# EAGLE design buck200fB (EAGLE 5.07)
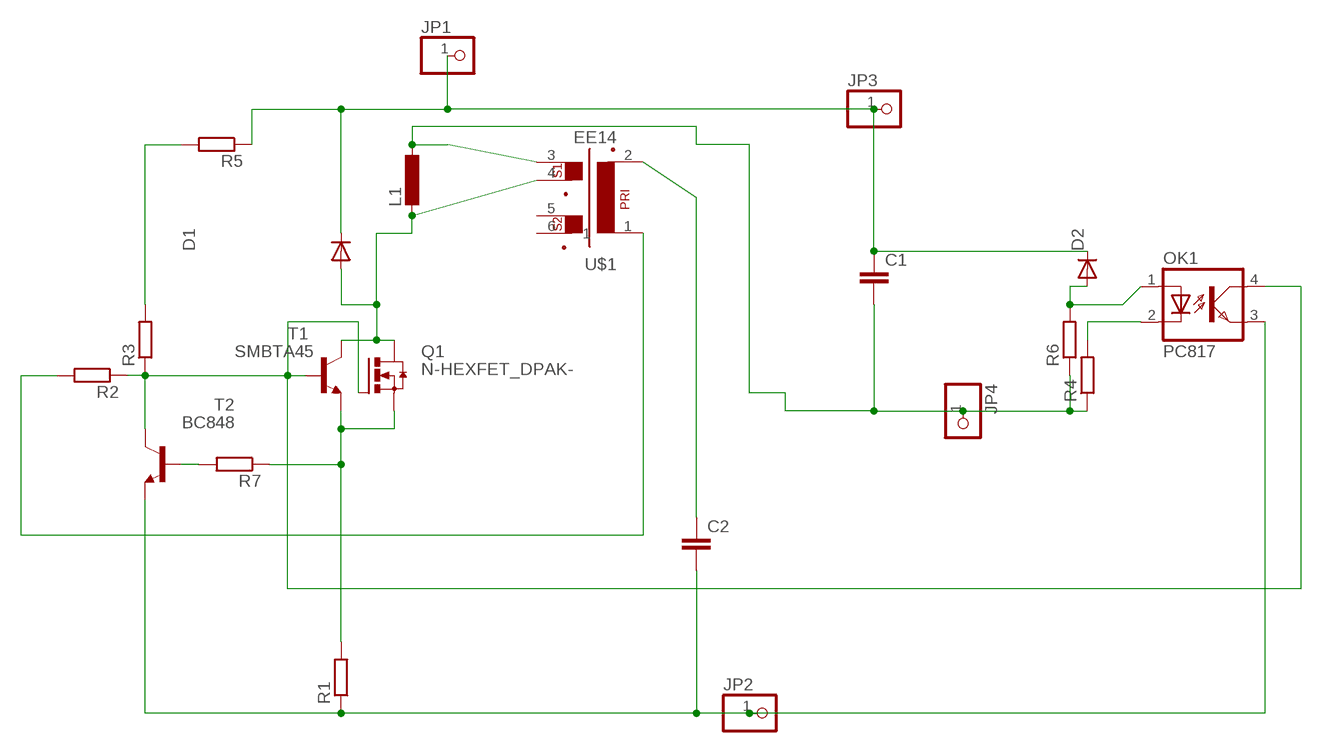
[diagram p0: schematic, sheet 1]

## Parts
C1  C-EU025-025X050  [C025-025X050]
C2  C-EUC0805  [C0805]
D1  DIODE-SMC  [SMC]
D2  DIODE-MINIMELF  [MINIMELF]
JP1  PINHD-1X11MM6  [1X1MM8]
JP2  PINHD-1X11MM6  [1X1MM8]
JP3  PINHD-1X11MM6  [1X1MM8]
JP4  PINHD-1X11MM6  [1X1MM8]
L1  L-EU0204/5  [0204/5]
OK1  PC817  [DIL04]
Q1  N-HEXFET_DPAK-  [TO252]
R1  R-EU_R0805  [R0805]
R2  R-EU_R0805  [R0805]
R3  R-EU_R1206  [R1206]
R4  R-EU_R0805  [R0805]
R5  R-EU_R1206  [R1206]
R6  R-EU_R0805  [R0805]
R7  R-EU_R0805  [R0805]
T1  SMBTA45  BC848  [SOT23]
T2  BC848  [SOT23]
U$1  EE14  [EE14]

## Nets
B1C2: OK1.4(COL) Q1.1(G) R2.1 R3.1 T1.B T2.C
C1: D1.A L1.2 Q1.3(D) T1.C U$1.4
EB: Q1.2(S) R1.2 R7.1 T1.E
N$1: R3.2 R5.2
N$3: R7.2 T2.B
N$4: R2.2 U$1.1
N$5: C1.2 JP4.1 L1.1 R4.1 R6.1 U$1.3
N$6: C2.1 U$1.2
N$7: D2.A OK1.1(A) R6.2
N$8: OK1.2(C) R4.2
V+: C1.1 D1.C D2.C JP1.1 JP3.1 R5.1
V-: C2.2 JP2.1 OK1.3(EMIT) R1.1 T2.E
Unconnected: U$1.5 U$1.6

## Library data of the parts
C1 C2 = rcl:C-EU: CAPACITOR, European symbol
D1 D2 = diode:DIODE-: DIODE
JP1-JP4 = pinhead:PINHD-1X1: PIN HEADER
L1 = rcl:L-EU: INDUCTOR, European symbol
OK1 = optocoupler:PC817: SHARP OPTO COUPLER
Q1 = transistor-power:N-HEXFET_?-*: HEXFET® Power MOSFET
R1-R7 = rcl:R-EU_: RESISTOR, European symbol
T1 T2 = transistor:BC848: NPN TRANSISTOR
U$1 = trafo:EE14

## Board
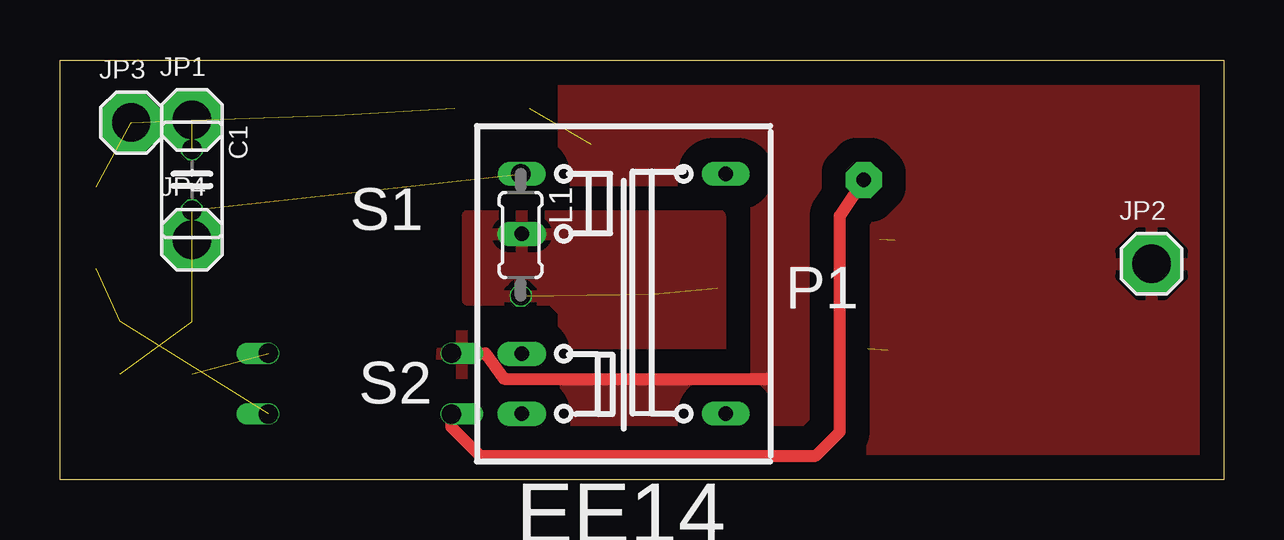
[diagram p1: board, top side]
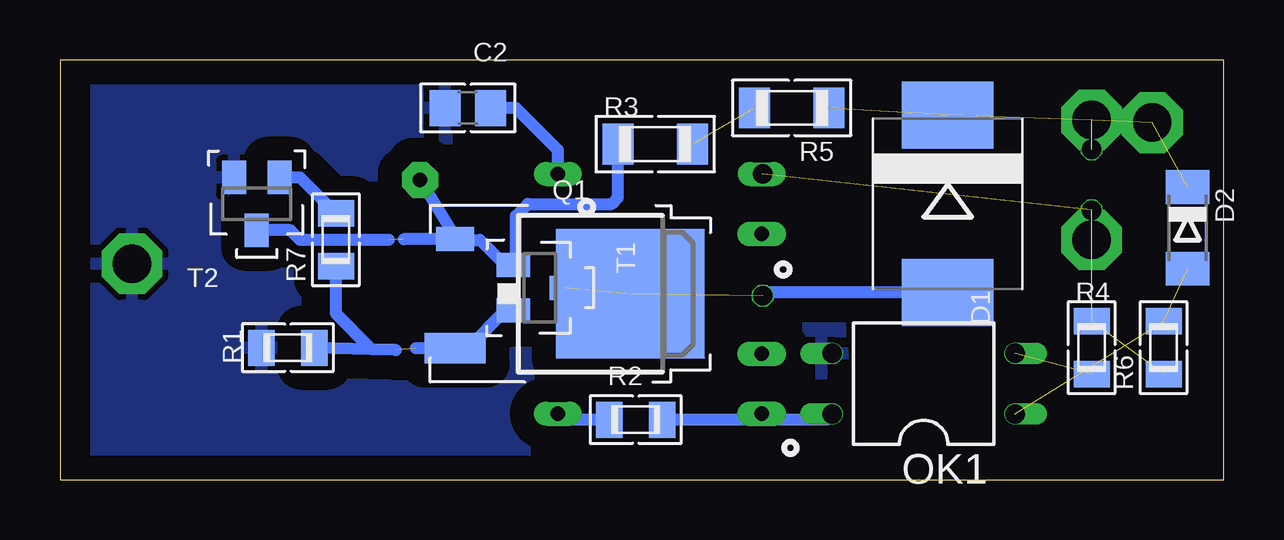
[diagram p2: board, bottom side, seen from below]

Size 48.5 x 17.5 mm. Coordinates in mm from the lower left corner, seen from the top.
Outline: 0,17.5 48.5,17.5 48.5,0 0,0 0,17.5
Copper layers (1*16): Top 0.035mm / dielectric 1.5mm / Bottom 0.035mm
Design rules "default": minimum track width 10mil, minimum drill 20mil, track to track 8mil, track to pad 8mil, pad to pad 8mil, via to via 8mil, smd to smd 8mil, copper to edge 40mil, drill to drill 8mil, minimum pad ring 1mil, minimum via ring 8mil, stop-mask expansion 4mil, vias tented up to drill 0mil, thermal gap 10mil

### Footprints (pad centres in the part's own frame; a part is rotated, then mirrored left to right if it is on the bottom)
C025-025X050 = drill 0.813 octagon: 1 -1.27,0; 2 1.27,0
C0805 = smd 1.3 x 1.5: 1 -0.95,0; 2 0.95,0
SMC = smd 2.8 x 3.8: A 3.7,0; C -3.7,0
MINIMELF = smd 1.4 x 1.8: A 1.7,0; C -1.7,0
1X1MM8 = drill 1.6 pad 2.54 octagon: 1 0,0
0204/5 = drill 0.813 octagon: 1 -2.54,0; 2 2.54,0
DIL04 = drill 0.813 offset: 1 -1.27,-3.81; 2 1.27,-3.81; 3 1.27,3.81; 4 -1.27,3.81
TO252 = smd 1 x 1.6: 1 -2.28,-3.53 | smd 1.27 x 2.54: 2 2.28,-3.53 | smd 5.4 x 6.2: 3 0,3.77
R0805 = smd 1.1 x 1.5: 1 -1.1,0; 2 1.1,0
R1206 = smd 1.3 x 1.7: 1 -1.55,0; 2 1.55,0
SOT23 = smd 1 x 1.4: B -0.95,-1.1; C 0,1.1; E 0.95,-1.1
EE14 = drill 0.6 pad 1 long: 1 4.25,-5; 2 4.25,5; 3 -4.25,5 | drill 0.6 pad 1.016 long: 4 -4.25,2.5; 5 -4.25,-2.5; 6 -4.25,-5

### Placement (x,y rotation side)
C1  5.5,12.5 270 top
C2  31.5,15.5 180 bottom
D1  11.5,11.5 270 bottom
D2  1.5,10.5 270 bottom
JP1  5.5,15 0 top
JP2  45.5,9 0 top
JP3  2.97,14.89 0 top
JP4  5.5,10 0 top
L1  19.2,10.2 270 top
OK1  12.5,4 90 bottom
Q1  28.5,7.75 270 bottom
R1  39,5.5 0 bottom
R2  24.5,2.5 180 bottom
R3  23.69,13.99 0 bottom
R4  5.5,5.5 270 bottom
R5  18,15.5 180 bottom
R6  2.5,5.5 90 bottom
R7  37,10 90 bottom
T1  28.5,8 270 bottom
T2  40.3,11.5 180 bottom
U$1  23.5,7.75 0 top

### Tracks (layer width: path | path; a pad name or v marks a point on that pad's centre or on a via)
B1C2  (via drill 0.6 pad 1.5)  (1 unrouted)
  Top 0.5: OK1.4 16.31,2.19 17.5,1 31.5,1 32.5,2 32.5,11 v33.5,12.5
  Bottom 0.5: R3.1 25.24,11.76 25.5,11.5 29,11.5 29.5,11 29.5,9.05 T1.B 29.95,8.95 31,10 32,10 Q1.1 | Q1.1 34.17,10.03 | T2.C 38.9,10.4 38.5,10 34.8,10 | v33.5,12.5 32,10.06 Q1.1 | R2.1 16.54,2.5 OK1.4
C1  (2 unrouted)
  Bottom 0.5: D1.A 19.06,7.8 L1.2
  pour Top (isolate 1, rank 2): 21,11 27.5,11 27.5,5 21,5 21,7 20.5,7.5 17,7.5 17,11
EB  (1 unrouted)
  Bottom 0.5: T1.E 29.95,7.05 31.5,5.5 32,5.5 Q1.2 33.67,5.47 | 34.5,5.4 35.5,5.43 | 35.5,5.43 R1.2 | R7.1 37,6.93 35.5,5.43
N$1  (1 unrouted)
N$3
  Bottom 0.5: T2.B 38.5,12.6 R7.2
N$4
  Bottom 0.5: R2.2 27.5,2.5 U$1.1
N$5  (5 unrouted)
N$6
  Bottom 0.5: U$1.2 27.75,13.75 29.5,15.5 C2.1
N$7  (2 unrouted)
N$8  (1 unrouted)
V+  (5 unrouted)
V-
  Top 0.5: OK1.3 17.73,5.27 18.5,4.2 29.5,4.2
  pour Top (isolate 1, rank 3): 21,16.5 48,16.5 48,0.5 15.5,0.5 16,6 21,6
  pour Bottom (isolate 1, rank 3): 21,17 47,17 47,1 15.5,1 16,6.5 22,6.5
